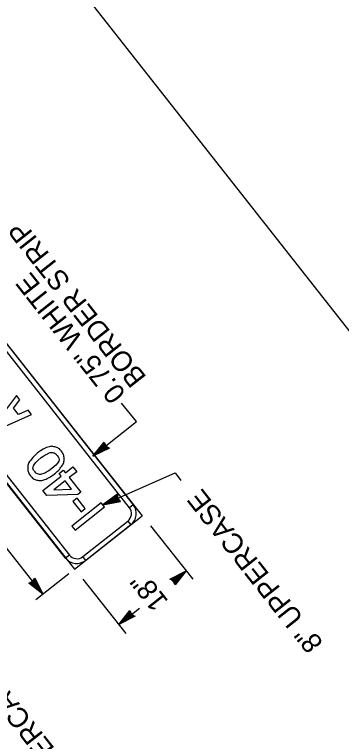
# Model space of a CAD drawing. Extents: x 672126 to 673696, y 1673540 to 1674900.
# Drawn here: x 672307.3 to 672375.7, y 1674609.9 to 1674761.8 of the extents above; entities that cross this region are included whole.
import ezdxf

# ---------------------------------------------------------------- set-up
doc = ezdxf.new("R2010")
doc.units = 0
for name, color, linetype in [('61', 7, 'Continuous'), ('C-ANNO-SYMB', 7, 'Continuous'), ('Level 1', 7, 'Continuous')]:
    doc.layers.add(name, color=color, linetype=linetype)

msp = doc.modelspace()

# ---------------------------------------------------------------- linework, layer by layer
at = {"layer": '61'}
msp.add_lwpolyline([(672517.13, 1674725.06), (672386.09, 1674891.28), (672285.59, 1674812.06), (672416.63, 1674645.83)], close=True, dxfattribs=at)
at = {"layer": 'C-ANNO-SYMB'}
for p, q in [((672289.4, 1674713.6), (672333.97, 1674657.06)), ((672275.26, 1674702.46), (672319.84, 1674645.91)), ((672332.12, 1674659.41), (672331.33, 1674658.79)), ((672319.84, 1674645.91), (672333.97, 1674657.06)), ((672331, 1674655.99), (672331.62, 1674655.2)), ((672318.77, 1674648.89), (672317.98, 1674648.27)), ((672322.19, 1674647.77), (672321.57, 1674648.56))]:
    msp.add_line(p, q, dxfattribs=at)
for points in [[(672331.33, 1674658.79), (672290.47, 1674710.62), (672291.26, 1674711.24), (672332.12, 1674659.41), (672331.33, 1674658.79), (672331.33, 1674658.79)], [(672277.91, 1674700.72), (672318.77, 1674648.89), (672317.98, 1674648.27), (672277.12, 1674700.1), (672277.91, 1674700.72), (672277.91, 1674700.72)], [(672326.12, 1674658.94), (672325.44, 1674659.81), (672319.28, 1674654.95), (672319.96, 1674654.08)], [(672322.08, 1674658.6), (672320.37, 1674660.78), (672319.52, 1674660.11), (672321.23, 1674657.93)], [(672321.57, 1674648.56), (672331, 1674655.99), (672331.62, 1674655.2), (672322.19, 1674647.77), (672321.57, 1674648.56), (672321.57, 1674648.56)]]:
    msp.add_lwpolyline(points, close=True, dxfattribs=at)
for points in [[(672310.87, 1674678.29), (672310.17, 1674679.18), (672308.14, 1674678.26), (672307.09, 1674679.59), (672308.44, 1674681.36), (672307.73, 1674682.26), (672302.8, 1674675.85), (672303.48, 1674674.98), (672310.87, 1674678.29)], [(672316.62, 1674665.95), (672317.5, 1674666.65), (672317.96, 1674666.06), (672319.53, 1674667.3), (672320.31, 1674666.31), (672318.74, 1674665.07), (672321.14, 1674662.03), (672320.55, 1674661.57), (672314.03, 1674661.36), (672313.25, 1674662.35), (672317.08, 1674665.37), (672316.62, 1674665.95)], [(672319.22, 1674662.65), (672317.86, 1674664.38), (672315.51, 1674662.53), (672319.22, 1674662.65)]]:
    msp.add_lwpolyline(points, dxfattribs=at)
for centre, radius, start, end in [((672329.76, 1674657.56), 2, 308.2504, 38.2506), ((672329.76, 1674657.56), 3, 308.2504, 38.2506), ((672320.34, 1674650.13), 2, 218.2508, 308.2504), ((672320.34, 1674650.13), 3, 218.2508, 308.2504)]:
    msp.add_arc(centre, radius, start, end, dxfattribs=at)
for points in [[(672312.12, 1674670.23), (672313.08, 1674670.99), (672314.13, 1674671.39), (672314.92, 1674671.7), (672315.76, 1674671.48), (672316.56, 1674671.26), (672317.1, 1674670.57), (672317.64, 1674669.89), (672317.66, 1674669.05), (672317.69, 1674668.19), (672317.19, 1674667.48), (672316.54, 1674666.56), (672315.6, 1674665.82), (672314.67, 1674665.08), (672313.62, 1674664.67), (672312.8, 1674664.36), (672311.99, 1674664.57), (672311.17, 1674664.79), (672310.63, 1674665.47), (672310.1, 1674666.15), (672310.08, 1674667), (672310.05, 1674667.86), (672310.54, 1674668.56), (672311.18, 1674669.49), (672312.12, 1674670.23)], [(672312.89, 1674669.26), (672310.64, 1674667.48), (672311.6, 1674666.25), (672311.89, 1674665.89), (672312.31, 1674665.78), (672312.73, 1674665.67), (672313.15, 1674665.83), (672314.03, 1674666.17), (672314.83, 1674666.8), (672317.09, 1674668.58), (672316.12, 1674669.81), (672315.83, 1674670.17), (672315.42, 1674670.28), (672315.01, 1674670.39), (672314.58, 1674670.23), (672313.69, 1674669.89), (672312.89, 1674669.26)]]:
    msp.add_open_spline(points, degree=3, dxfattribs=at)
at = {"layer": 'Level 1'}
for p, q in [((672323.7, 1674669.55), (672326.02, 1674672.46)), ((672323.92, 1674669.78), (672326, 1674672.31)), ((672324.27, 1674670.06), (672326, 1674672.14)), ((672324.49, 1674670.16), (672326.04, 1674671.87)), ((672324.56, 1674670.28), (672326, 1674672.01)), ((672324.99, 1674670.62), (672325.99, 1674671.73)), ((672325.38, 1674670.89), (672325.95, 1674671.6)), ((672326.05, 1674671.74), (672325.54, 1674670.98)), ((672325.95, 1674671.6), (672326.23, 1674671.46)), ((672325.99, 1674671.73), (672326.34, 1674671.41)), ((672326, 1674672.31), (672326.34, 1674671.74)), ((672326, 1674672.14), (672326.14, 1674671.88)), ((672326, 1674672.01), (672326.68, 1674671.31)), ((672326.02, 1674672.46), (672326.41, 1674671.7)), ((672326.04, 1674671.87), (672326.5, 1674671.37)), ((672326.42, 1674671.47), (672326.05, 1674671.74)), ((672326.14, 1674671.88), (672326.68, 1674671.31)), ((672326.34, 1674671.74), (672327.01, 1674671.27)), ((672326.41, 1674671.7), (672326.65, 1674671.39)), ((672327.16, 1674671.25), (672323.7, 1674669.55)), ((672326.8, 1674671.24), (672323.96, 1674669.81)), ((672326.97, 1674671.2), (672324.12, 1674669.91)), ((672326.68, 1674671.31), (672324.49, 1674670.16)), ((672326.68, 1674671.31), (672324.56, 1674670.28)), ((672326.5, 1674671.37), (672324.99, 1674670.62)), ((672325.54, 1674670.98), (672325.29, 1674670.88)), ((672326.34, 1674671.41), (672325.38, 1674670.89)), ((672325.72, 1674671.19), (672325.98, 1674671.53)), ((672326.23, 1674671.46), (672325.72, 1674671.19)), ((672325.98, 1674671.53), (672326.06, 1674671.46)), ((672326.06, 1674671.46), (672326.42, 1674671.47)), ((672326.65, 1674671.39), (672326.97, 1674671.2)), ((672327.01, 1674671.27), (672326.79, 1674671.33)), ((672326.79, 1674671.33), (672326.8, 1674671.24)), ((672328.9, 1674661.68), (672325.78, 1674659.41)), ((672328.73, 1674661.37), (672326.14, 1674659.52)), ((672328.77, 1674661.54), (672326.3, 1674659.62)), ((672328.73, 1674661.23), (672326.69, 1674659.82)), ((672328.73, 1674661.23), (672326.84, 1674659.83)), ((672328.7, 1674661.04), (672327.34, 1674660.06)), ((672328.93, 1674660.4), (672328.7, 1674661.04)), ((672328.81, 1674661.32), (672328.73, 1674661.37)), ((672328.98, 1674660.48), (672328.73, 1674661.23)), ((672329.03, 1674660.3), (672328.73, 1674661.23)), ((672328.79, 1674661.17), (672328.77, 1674661.54)), ((672328.95, 1674660.81), (672328.79, 1674661.17)), ((672328.85, 1674661.54), (672328.81, 1674661.32)), ((672328.96, 1674660.73), (672328.85, 1674661.54)), ((672325.78, 1674659.41), (672329.44, 1674660.11)), ((672326.09, 1674659.49), (672329.3, 1674660.16)), ((672326.3, 1674659.62), (672326.09, 1674659.49)), ((672326.14, 1674659.52), (672326.26, 1674659.69)), ((672326.26, 1674659.69), (672327.01, 1674660.2)), ((672326.5, 1674659.68), (672329.15, 1674660.24)), ((672327.01, 1674660.2), (672326.5, 1674659.68)), ((672326.69, 1674659.82), (672328.93, 1674660.4)), ((672326.84, 1674659.83), (672329.03, 1674660.3)), ((672327.23, 1674660.04), (672327.62, 1674660.32)), ((672327.71, 1674660.19), (672327.23, 1674660.04)), ((672327.34, 1674660.06), (672328.78, 1674660.42)), ((672327.91, 1674660.37), (672327.71, 1674660.19)), ((672328.66, 1674660.88), (672327.76, 1674660.27)), ((672327.76, 1674660.27), (672328.65, 1674660.45)), ((672328.82, 1674660.47), (672327.91, 1674660.37)), ((672328.65, 1674660.76), (672328.17, 1674660.43)), ((672328.17, 1674660.43), (672328.6, 1674660.51)), ((672328.58, 1674660.61), (672328.75, 1674660.92)), ((672328.6, 1674660.51), (672328.58, 1674660.61)), ((672328.65, 1674660.45), (672328.65, 1674660.76)), ((672328.78, 1674660.42), (672328.66, 1674660.88)), ((672328.75, 1674660.92), (672328.82, 1674660.47)), ((672329.44, 1674660.11), (672328.95, 1674660.81)), ((672329.3, 1674660.16), (672328.96, 1674660.73)), ((672329.15, 1674660.24), (672328.98, 1674660.48)), ((672313.22, 1674640.7), (672298.61, 1674659.24)), ((672335.76, 1674655.02), (672344.59, 1674643.82)), ((672318.68, 1674645), (672311.78, 1674639.56)), ((672339.76, 1674643.85), (672343.22, 1674645.56)), ((672339.95, 1674643.9), (672342.8, 1674645.2)), ((672340.12, 1674643.87), (672342.96, 1674645.29)), ((672340.24, 1674643.79), (672342.43, 1674644.94)), ((672340.24, 1674643.79), (672342.36, 1674644.82)), ((672340.42, 1674643.74), (672341.93, 1674644.48)), ((672342.43, 1674644.94), (672340.88, 1674643.23)), ((672343.22, 1674645.56), (672340.9, 1674642.65)), ((672343, 1674645.32), (672340.92, 1674642.8)), ((672342.65, 1674645.04), (672340.92, 1674642.96)), ((672342.36, 1674644.82), (672340.92, 1674643.1)), ((672341.93, 1674644.48), (672340.93, 1674643.37)), ((672342, 1674644.57), (672341.56, 1674644.36)), ((672341.63, 1674644.22), (672342, 1674644.57)), ((672342.75, 1674645.26), (672341.95, 1674644.83)), ((672341.95, 1674644.83), (672342.65, 1674645.04)), ((672342.96, 1674645.29), (672342.75, 1674645.26)), ((672342.8, 1674645.2), (672343, 1674645.32)), ((672310.31, 1674643.02), (672311.07, 1674643.41)), ((672313.22, 1674640.7), (672310.31, 1674643.02)), ((672310.46, 1674643), (672311.03, 1674643.34)), ((672312.99, 1674640.92), (672310.46, 1674643)), ((672310.63, 1674643), (672310.89, 1674643.14)), ((672312.71, 1674641.27), (672310.63, 1674643)), ((672310.76, 1674643), (672311.46, 1674643.68)), ((672312.49, 1674641.56), (672310.76, 1674643)), ((672310.89, 1674643.14), (672311.46, 1674643.68)), ((672310.89, 1674643.04), (672311.4, 1674643.5)), ((672312.61, 1674641.49), (672310.89, 1674643.04)), ((672311.03, 1674643.34), (672311.5, 1674644.01)), ((672311.3, 1674643.42), (672311.03, 1674643.04)), ((672311.03, 1674643.04), (672311.78, 1674642.54)), ((672311.04, 1674642.99), (672311.36, 1674643.34)), ((672312.15, 1674641.99), (672311.04, 1674642.99)), ((672311.07, 1674643.41), (672311.38, 1674643.65)), ((672311.17, 1674642.95), (672311.31, 1674643.23)), ((672311.88, 1674642.38), (672311.17, 1674642.95)), ((672311.24, 1674642.98), (672311.31, 1674643.06)), ((672311.58, 1674642.71), (672311.24, 1674642.98)), ((672311.31, 1674643.06), (672311.3, 1674643.42)), ((672311.31, 1674643.23), (672311.58, 1674642.71)), ((672311.36, 1674643.34), (672311.88, 1674642.38)), ((672311.38, 1674643.65), (672311.57, 1674643.97)), ((672311.4, 1674643.5), (672312.15, 1674641.99)), ((672311.5, 1674644.01), (672311.44, 1674643.79)), ((672311.44, 1674643.79), (672311.53, 1674643.8)), ((672311.46, 1674643.68), (672312.49, 1674641.56)), ((672311.46, 1674643.68), (672312.61, 1674641.49)), ((672311.52, 1674644.16), (672313.22, 1674640.7)), ((672311.53, 1674643.8), (672312.95, 1674640.96)), ((672311.57, 1674643.97), (672312.86, 1674641.12)), ((672321.62, 1674643.88), (672330.58, 1674632.52)), ((672340.58, 1674643.36), (672339.91, 1674643.83)), ((672339.91, 1674643.83), (672340.13, 1674643.77)), ((672340.27, 1674643.72), (672339.95, 1674643.9)), ((672340.13, 1674643.77), (672340.12, 1674643.87)), ((672340.78, 1674643.22), (672340.24, 1674643.79)), ((672340.92, 1674643.1), (672340.24, 1674643.79)), ((672340.51, 1674643.41), (672340.27, 1674643.72)), ((672340.88, 1674643.23), (672340.42, 1674643.74)), ((672340.86, 1674643.64), (672340.5, 1674643.63)), ((672340.5, 1674643.63), (672340.88, 1674643.36)), ((672340.9, 1674642.65), (672340.51, 1674643.41)), ((672340.58, 1674643.7), (672341.54, 1674644.21)), ((672340.93, 1674643.37), (672340.58, 1674643.7)), ((672340.92, 1674642.8), (672340.58, 1674643.36)), ((672340.69, 1674643.65), (672341.2, 1674643.92)), ((672340.97, 1674643.5), (672340.69, 1674643.65)), ((672340.92, 1674642.96), (672340.78, 1674643.22)), ((672340.94, 1674643.58), (672340.86, 1674643.64)), ((672340.88, 1674643.36), (672341.38, 1674644.12)), ((672341.2, 1674643.92), (672340.94, 1674643.58)), ((672341.54, 1674644.21), (672340.97, 1674643.5)), ((672341.38, 1674644.12), (672341.63, 1674644.22)), ((672311.78, 1674642.54), (672311.89, 1674642.28)), ((672311.89, 1674642.28), (672312.23, 1674641.92)), ((672312.23, 1674641.92), (672312.03, 1674642.36)), ((672312.92, 1674641.16), (672312.5, 1674641.96)), ((672312.5, 1674641.96), (672312.71, 1674641.27)), ((672312.86, 1674641.12), (672312.99, 1674640.92)), ((672312.95, 1674640.96), (672312.92, 1674641.16)), ((672329.09, 1674634.41), (672333.41, 1674637.82)), ((672329.09, 1674634.41), (672331.41, 1674637.32)), ((672329.3, 1674634.65), (672331.39, 1674637.17)), ((672329.65, 1674634.92), (672331.39, 1674637)), ((672329.87, 1674635.02), (672331.43, 1674636.74)), ((672329.95, 1674635.15), (672331.39, 1674636.87)), ((672331.39, 1674637.17), (672331.73, 1674636.61)), ((672331.39, 1674637), (672331.52, 1674636.74)), ((672331.39, 1674636.87), (672332.07, 1674636.17)), ((672331.41, 1674637.32), (672331.8, 1674636.56)), ((672331.43, 1674636.74), (672331.89, 1674636.23)), ((672331.52, 1674636.74), (672332.07, 1674636.17)), ((672332.55, 1674636.12), (672329.09, 1674634.41)), ((672332.19, 1674636.1), (672329.35, 1674634.68)), ((672332.36, 1674636.06), (672329.51, 1674634.77)), ((672329.55, 1674634.71), (672330.35, 1674635.13)), ((672330.35, 1674635.13), (672329.65, 1674634.92)), ((672332.07, 1674636.17), (672329.87, 1674635.02)), ((672332.07, 1674636.17), (672329.95, 1674635.15)), ((672330.67, 1674635.75), (672330.31, 1674635.4)), ((672330.31, 1674635.4), (672330.75, 1674635.61)), ((672330.38, 1674635.49), (672331.37, 1674636.59)), ((672331.89, 1674636.23), (672330.38, 1674635.49)), ((672330.93, 1674635.85), (672330.67, 1674635.75)), ((672330.77, 1674635.76), (672331.34, 1674636.47)), ((672331.73, 1674636.27), (672330.77, 1674635.76)), ((672331.43, 1674636.61), (672330.93, 1674635.85)), ((672331.1, 1674636.05), (672331.37, 1674636.39)), ((672331.62, 1674636.32), (672331.1, 1674636.05)), ((672331.34, 1674636.47), (672331.62, 1674636.32)), ((672331.37, 1674636.59), (672331.73, 1674636.27)), ((672331.37, 1674636.39), (672331.45, 1674636.32)), ((672331.81, 1674636.34), (672331.43, 1674636.61)), ((672331.45, 1674636.32), (672331.81, 1674636.34)), ((672331.73, 1674636.61), (672332.4, 1674636.13)), ((672331.8, 1674636.56), (672332.04, 1674636.25)), ((672332.04, 1674636.25), (672332.36, 1674636.06)), ((672332.4, 1674636.13), (672332.18, 1674636.2)), ((672332.18, 1674636.2), (672332.19, 1674636.1)), ((672329.51, 1674634.77), (672329.3, 1674634.65)), ((672329.35, 1674634.68), (672329.55, 1674634.71))]:
    msp.add_line(p, q, dxfattribs=at)
for points in [[(672323.7, 1674669.55), (672332.81, 1674676.81), (672329.68, 1674680.66)], [(672325.78, 1674659.41), (672340.89, 1674666.05), (672342.12, 1674664.5)]]:
    msp.add_lwpolyline(points, dxfattribs=at)

# ---------------------------------------------------------------- texts
for s, p in [('BORDER STRIP', (672335.04, 1674686.06)), ('0.75" WHITE ', (672330.75, 1674682.67)), ('8" UPPERCASE', (672372.04, 1674630.55)), ('18"', (672339.63, 1674639.25)), ('8" UPPERCASE', (672327.11, 1674594.13))]:
    msp.add_text(s, height=4.2, rotation=128.2505, dxfattribs=at).set_placement(p)

doc.saveas('drawing.dxf')
